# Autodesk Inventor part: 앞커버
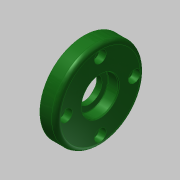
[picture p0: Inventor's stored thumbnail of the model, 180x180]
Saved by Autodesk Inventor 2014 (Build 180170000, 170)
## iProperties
Created: 2015-11
Part Number: 앞커버
Material: 알루미늄 6061
Document SubType Name: Modeling
Designer: mduedu
Density: 1 g/cm^3
Appearance: 매끄러움 - 짙은 산림 녹색
Author: mduedu
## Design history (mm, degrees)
sketch "스케치5"
  geometry: C1 r 30 at (0, 0); 2 further points
  constraints: 2 coincident, 1 centre point
  dimensions: "d66" = 60 diameter of C1
extrude "돌출2" new body sketch "스케치5" distance "d67" = 11; taper "d68" = 0 deg
sketch "스케치6"
  geometry: C1 r 16 at (0, 0); 1 further point
  constraints: 1 centre point, 1 coincident
  dimensions: "d69" = 32 diameter of C1
extrude "돌출3" join sketch "스케치6" distance "d70" = 3; taper "d71" = 0 deg
hole "구멍7" diameter "d98" = 25; stored, may be unused: countersink angle "d102" = 90 deg, drill point angle "d104" = 0 deg; dims "d96" = 10, "d97" = 10, "d99" = 6, "d100" = 4, "d101" = 2, "d103" = 3
hole "구멍8" diameter "d107" = 25; stored, may be unused: countersink angle "d111" = 90 deg, drill point angle "d113" = 0 deg; dims "d108" = 6, "d109" = 4, "d110" = 2, "d112" = 7.3, "d143" = 10, "d144" = 10
hole "구멍9" diameter "d116" = 17; stored, may be unused: countersink angle "d120" = 90 deg, drill point angle "d122" = 0 deg; dims "d114" = 10, "d115" = 10, "d117" = 6, "d118" = 4, "d119" = 2, "d121" = 7.7
chamfer "모따기2" distance "d123" = 0.7; stored, may be unused: second distance "d124" = 2, angle "d125" = 30 deg
fillet "모깎기11" dims "d126" = 0.3
fillet "모깎기13" dims "d128" = 3
fillet "모깎기14" dims "d129" = 3
fillet "모깎기15" dims "d130" = 0.3
sketch "스케치8" dims "d131" = 46
  geometry: 3 further points
  constraints: 2 vertical alignment, 1 coincident, 2 other
hole "구멍10" sketch "스케치8" at (0, 23) diameter "d132" = 4.5; stored, may be unused: countersink angle "d136" = 90 deg, drill point angle "d138" = 0 deg; dims "d133" = 6, "d134" = 8, "d135" = 4.6, "d137" = 7.7
node "솔리드2"
pattern_circular "원형 패턴4" dims angle "d140" = 360 deg
